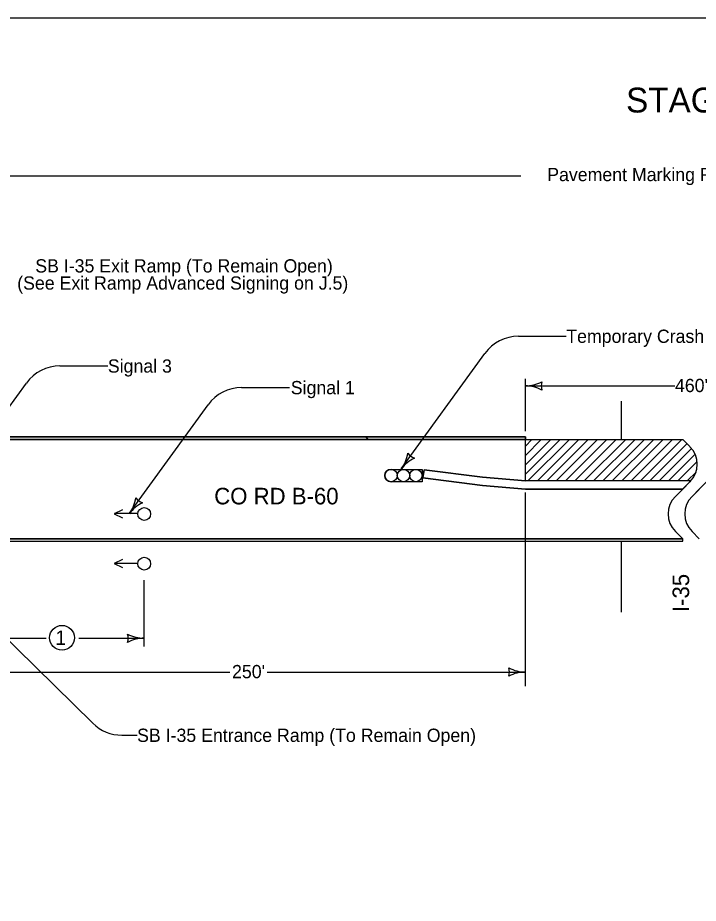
# Model space of a CAD drawing. Extents: x -2134934 to -2122394, y -2139046 to -2137036.
# Drawn here: x -2134187 to -2133366, y -2138105 to -2137036 of the extents above; entities that cross this region are included whole.
import ezdxf

# ---------------------------------------------------------------- set-up
doc = ezdxf.new("R2010")
doc.units = 0
for name, color, linetype in [('Barrier', 7, 'Continuous'), ('BridgeSuperStructureExisting', 7, 'Continuous'), ('Default', 7, 'Continuous'), ('dsnCellsNorthArrow', 7, 'Continuous'), ('DsnShtPlotIdentification', 7, 'Continuous'), ('DsnShtPlotShape', 7, 'Continuous')]:
    doc.layers.add(name, color=color, linetype=linetype)

msp = doc.modelspace()

# ---------------------------------------------------------------- linework, layer by layer
at = {"layer": 'BridgeSuperStructureExisting'}
for p, q in [((-2134239.4, -2137227), (-2133580, -2137227)), ((-2133582.7, -2137420.6), (-2133525, -2137420.6)), ((-2133724.1, -2137580.8), (-2133623.3, -2137441.3)), ((-2134136.1, -2137456.5), (-2134078.3, -2137456.5)), ((-2133574.4, -2137535.2), (-2133574.4, -2137471.9)), ((-2134351.4, -2137719), (-2134176.6, -2137477.2)), ((-2133916.8, -2137482.6), (-2133859, -2137482.6)), ((-2133574.4, -2137480.5), (-2133393.8, -2137480.5)), ((-2134052, -2137634.3), (-2133957.3, -2137503.3)), ((-2133458.6, -2137498.8), (-2133458.6, -2137545.2)), ((-2133574.4, -2137545.2), (-2134884.4, -2137545.2)), ((-2133574.4, -2137553.2), (-2133566.4, -2137545.2)), ((-2133574.4, -2137564.5), (-2133555.1, -2137545.2)), ((-2133574.4, -2137575.8), (-2133543.8, -2137545.2)), ((-2133574.4, -2137595.2), (-2133574.4, -2137545.2)), ((-2133574.4, -2137587.1), (-2133532.5, -2137545.2)), ((-2133574.4, -2137595.2), (-2133574.4, -2137545.2)), ((-2133571.2, -2137595.2), (-2133521.2, -2137545.2)), ((-2133559.9, -2137595.2), (-2133509.9, -2137545.2)), ((-2133548.6, -2137595.2), (-2133498.6, -2137545.2)), ((-2133537.3, -2137595.2), (-2133487.3, -2137545.2)), ((-2133525.9, -2137595.2), (-2133475.9, -2137545.2)), ((-2133514.6, -2137595.2), (-2133464.6, -2137545.2)), ((-2133453.3, -2137545.2), (-2133503.3, -2137595.2)), ((-2133492, -2137595.2), (-2133442, -2137545.2)), ((-2133480.7, -2137595.2), (-2133430.7, -2137545.2)), ((-2133469.4, -2137595.2), (-2133419.4, -2137545.2)), ((-2133458.1, -2137595.2), (-2133408.1, -2137545.2)), ((-2133446.7, -2137595.2), (-2133396.7, -2137545.2)), ((-2133435.4, -2137595.2), (-2133385.4, -2137545.2)), ((-2133375.7, -2137553.9), (-2133384.4, -2137545.2)), ((-2133424.1, -2137595.2), (-2133379.3, -2137550.3)), ((-2133412.8, -2137595.2), (-2133373.7, -2137556.1)), ((-2133401.5, -2137595.2), (-2133369.4, -2137563.1)), ((-2133390.2, -2137595.2), (-2133367, -2137572)), ((-2133736.5, -2137581.3), (-2133699, -2137581.3)), ((-2133736.5, -2137581.3), (-2133699, -2137581.3)), ((-2133699, -2137581.3), (-2133699, -2137596.3)), ((-2133699, -2137581.3), (-2133699, -2137596.3)), ((-2133696.7, -2137581.7), (-2133698, -2137591.5)), ((-2133696.7, -2137581.7), (-2133698, -2137591.5)), ((-2133698, -2137591.5), (-2133696.7, -2137581.7)), ((-2133698, -2137591.5), (-2133696.7, -2137581.7)), ((-2133626.2, -2137590.8), (-2133696.7, -2137581.7)), ((-2133626.2, -2137590.8), (-2133696.7, -2137581.7)), ((-2133626.2, -2137590.8), (-2133696.7, -2137581.7)), ((-2133696.7, -2137581.7), (-2133626.2, -2137590.8)), ((-2133378.9, -2137595.2), (-2133368.4, -2137584.7)), ((-2133699, -2137596.3), (-2133736.5, -2137596.3)), ((-2133699, -2137596.3), (-2133736.5, -2137596.3)), ((-2133698, -2137591.5), (-2133626, -2137600.8)), ((-2133626, -2137600.8), (-2133698, -2137591.5)), ((-2133626, -2137600.8), (-2133698, -2137591.5)), ((-2133697.9, -2137591.5), (-2133626, -2137600.8)), ((-2133574.1, -2137595.2), (-2133626.2, -2137590.8)), ((-2133574.4, -2137595.1), (-2133626.2, -2137590.8)), ((-2133574.4, -2137595.2), (-2133626.2, -2137590.8)), ((-2133626.2, -2137590.8), (-2133574.4, -2137595.2)), ((-2133626, -2137600.8), (-2133574.4, -2137605.2)), ((-2133626, -2137600.8), (-2133574.4, -2137605.2)), ((-2133574.4, -2137605.2), (-2133626, -2137600.8)), ((-2133574.4, -2137605.2), (-2133626, -2137600.8)), ((-2133574.4, -2137595.2), (-2133574.4, -2137595.1)), ((-2133574.2, -2137595.2), (-2133574.4, -2137595.2)), ((-2133374.5, -2137595.2), (-2133574.4, -2137595.2)), ((-2133574.1, -2137595.2), (-2133574.2, -2137595.2)), ((-2133374.5, -2137595.2), (-2133574.1, -2137595.2)), ((-2133393.2, -2137613.9), (-2133375.7, -2137596.4)), ((-2133384.4, -2137605.2), (-2133375.7, -2137596.4)), ((-2133373.2, -2137613.9), (-2133355.7, -2137596.4)), ((-2133574.4, -2137605.2), (-2133384.4, -2137605.2)), ((-2133574.4, -2137605.2), (-2133384.4, -2137605.2)), ((-2133384.4, -2137605.2), (-2133574.4, -2137605.2)), ((-2133384.4, -2137605.2), (-2133574.4, -2137605.2)), ((-2133574.4, -2137843.1), (-2133574.4, -2137609.3)), ((-2133393.2, -2137613.9), (-2133384.4, -2137605.2)), ((-2134042.2, -2137634.8), (-2134070.1, -2137634.8)), ((-2134884.4, -2137665.2), (-2133384.4, -2137665.2)), ((-2133384.4, -2137665.2), (-2133393.2, -2137656.4)), ((-2133384.4, -2137665.2), (-2133393.2, -2137656.4)), ((-2133364.4, -2137665.2), (-2133373.2, -2137656.4)), ((-2133373.2, -2137656.4), (-2133364.4, -2137665.2)), ((-2133458.6, -2137668.2), (-2133458.6, -2137753.6)), ((-2134042.2, -2137694.8), (-2134070.1, -2137694.8)), ((-2134096.5, -2137887.9), (-2134284.7, -2137702.6)), ((-2134034.4, -2137795.2), (-2134034.4, -2137715.2)), ((-2134234.4, -2137785.2), (-2134152.7, -2137785.2)), ((-2134113.2, -2137785.2), (-2134034.4, -2137785.2)), ((-2134234.4, -2137826), (-2133930.9, -2137826)), ((-2133886, -2137826), (-2133574.4, -2137826)), ((-2133851.4, -2137826), (-2133801.8, -2137826)), ((-2134061.4, -2137902.3), (-2134043, -2137902.3))]:
    msp.add_line(p, q, dxfattribs=at)
for points in [[(-2133574.4, -2137545.2), (-2133384.4, -2137545.2)], [(-2133736.5, -2137581.3), (-2133736.5, -2137581.3)], [(-2133736.5, -2137596.3), (-2133736.5, -2137596.3)], [(-2133574.1, -2137595.2), (-2133574.1, -2137595.2)], [(-2133384.4, -2137605.2), (-2133384.4, -2137605.2)], [(-2133384.4, -2137605.2), (-2133384.4, -2137605.2)], [(-2133364.4, -2137605.2), (-2133364.4, -2137605.2), (-2133373.2, -2137613.9)], [(-2134060.5, -2137630), (-2134070.5, -2137635), (-2134060.5, -2137640)], [(-2134060.5, -2137690), (-2134070.5, -2137695), (-2134060.5, -2137700)]]:
    msp.add_lwpolyline(points, dxfattribs=at)
for centre, radius in [((-2133736.5, -2137588.8), 7.5), ((-2133736.5, -2137588.8), 7.5), ((-2133721.5, -2137588.8), 7.5), ((-2133721.5, -2137588.8), 7.5), ((-2133706.5, -2137588.8), 7.5), ((-2133706.5, -2137588.8), 7.5), ((-2134034.4, -2137635.2), 7.74), ((-2134034.4, -2137695.2), 7.74), ((-2134133.6, -2137784.7), 15)]:
    msp.add_circle(centre, radius, dxfattribs=at)
for centre, radius, start, end in [((-2133582.7, -2137470.6), 50, 90, 144.138), ((-2134136.1, -2137506.5), 50, 90, 144.138), ((-2133916.8, -2137532.6), 50, 90, 144.138), ((-2133574.4, -2137438), 42.5, 270, 298.0725), ((-2133574.4, -2137523), 42.5, 61.9275, 90), ((-2133538.8, -2137480.5), 16.4, 162.2666, 197.7334), ((-2133396.9, -2137575.2), 30, 315, 45), ((-2133736.5, -2137588.8), 7.5, 90.0028, 269.9972), ((-2133396.9, -2137575.2), 30, 315, 318.1884), ((-2133372, -2137635.2), 30, 135, 225), ((-2133372, -2137635.2), 30, 135, 225), ((-2133352, -2137635.2), 30, 135, 225), ((-2133352, -2137635.2), 30, 135, 225), ((-2134070.1, -2137785.2), 16.4, 342.2666, 17.7333), ((-2134034.4, -2137742.7), 42.5, 241.9275, 270), ((-2134034.4, -2137827.7), 42.5, 90, 118.0725), ((-2134061.4, -2137852.3), 50, 225.4365, 270)]:
    msp.add_arc(centre, radius, start, end, dxfattribs=at)
at = {"layer": 'Default'}
msp.add_lwpolyline([(-2134934.4, -2137035.9), (-2131799.4, -2137035.9), (-2131799.4, -2139045.9), (-2134934.4, -2139045.9)], close=True, dxfattribs=at)
at = {"layer": 'DsnShtPlotIdentification'}
for p, q in [((-2133766.5, -2137542.2), (-2134239.4, -2137542.2)), ((-2134239.4, -2137545.2), (-2133764.3, -2137545.2)), ((-2133574.4, -2137542.2), (-2133766.5, -2137542.2)), ((-2133766.5, -2137542.2), (-2133764.3, -2137545.2)), ((-2133764.3, -2137545.2), (-2133766.5, -2137542.2)), ((-2133574.4, -2137545.2), (-2133574.4, -2137542.2)), ((-2133574.4, -2137542.2), (-2133574.4, -2137545.2)), ((-2134884.4, -2137665.2), (-2133384.4, -2137665.2)), ((-2134884.4, -2137665.2), (-2133384.4, -2137665.2)), ((-2133384.4, -2137665.2), (-2134234.4, -2137665.2)), ((-2133384.4, -2137668.2), (-2133384.4, -2137665.2)), ((-2133384.4, -2137668.2), (-2133384.4, -2137665.2)), ((-2134884.4, -2137668.2), (-2133384.4, -2137668.2)), ((-2134884.4, -2137668.2), (-2133384.4, -2137668.2))]:
    msp.add_line(p, q, dxfattribs=at)
for points in [[(-2134884.9, -2137545.2), (-2133574.9, -2137545.2)], [(-2134884.4, -2137542.2), (-2133574.4, -2137542.2)], [(-2134884.4, -2137545.2), (-2133574.4, -2137545.2)], [(-2133764.3, -2137545.2), (-2133574.9, -2137545.2), (-2133574.4, -2137545.2)]]:
    msp.add_lwpolyline(points, dxfattribs=at)
at = {"layer": 'DsnShtPlotShape'}
for centre, radius, start, end in [((-2133758.3, -2137555.6), 42.5, 323.701, 351.7735), ((-2133689.8, -2137606), 42.5, 115.6285, 143.701), ((-2133703, -2137552.1), 16.4, 215.9676, 251.4343), ((-2134086.6, -2137609.6), 42.5, 323.701, 351.7735), ((-2134018.1, -2137660), 42.5, 115.6285, 143.701), ((-2134031.3, -2137606.1), 16.4, 215.9676, 251.4343), ((-2133610.1, -2137826), 16.4, 342.2666, 17.7333), ((-2133574.4, -2137783.5), 42.5, 241.9275, 270), ((-2133574.4, -2137868.5), 42.5, 90, 118.0725)]:
    msp.add_arc(centre, radius, start, end, dxfattribs=at)

# ---------------------------------------------------------------- texts
at = {"layer": 'Barrier'}
msp.add_text('STAGE 2', height=30, dxfattribs=at).set_placement((-2133452.8, -2137150.4))
at = {"layer": 'BridgeSuperStructureExisting'}
for s, height, p in [('Pavement Marking Removal Limits', 16, (-2133548, -2137233.3)), ('SB I-35 Exit Ramp (To Remain Open)', 16, (-2134165.9, -2137343.6)), ('(See Exit Ramp Advanced Signing on J.5)', 16, (-2134187.7, -2137364.3)), ('Temporary Crash Cushion', 16, (-2133525, -2137428.6)), ('Signal 3', 16, (-2134078.3, -2137464.5)), ("460'", 16, (-2133393.8, -2137488)), ('Signal 1', 16, (-2133857.5, -2137490.6)), ('1', 17.5, (-2134141.7, -2137793.4)), ("250'", 16, (-2133928.4, -2137833.5)), ('SB I-35 Entrance Ramp (To Remain Open)', 16, (-2134043, -2137910.4))]:
    msp.add_text(s, height=height, dxfattribs=at).set_placement(p)
at = {"layer": 'dsnCellsNorthArrow'}
msp.add_text('CO RD B-60', height=20, dxfattribs=at).set_placement((-2133949.9, -2137623.6))
msp.add_text('I-35', height=20, rotation=90, dxfattribs=at).set_placement((-2133376.7, -2137753.6))

doc.saveas('drawing.dxf')
